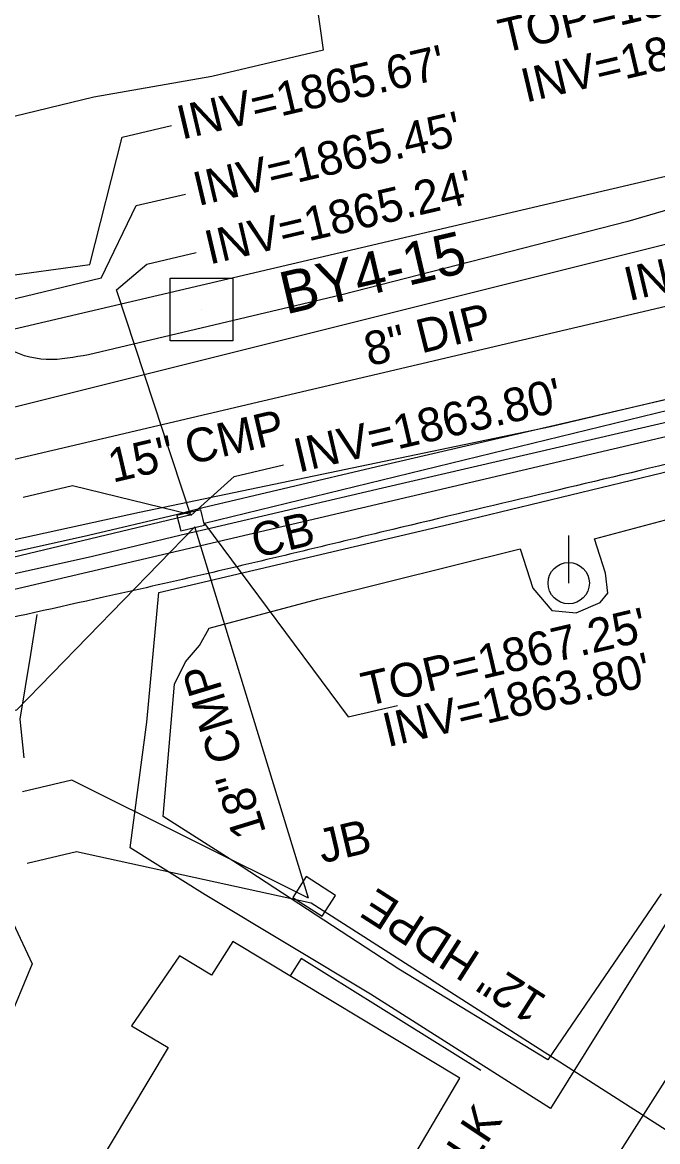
# Model space of a CAD drawing. Extents: x 553786 to 558838, y 502329 to 507342.
# Drawn here: x 557407.1 to 557482.4, y 506598.6 to 506731.1 of the extents above; entities that cross this region are included whole.
import ezdxf

# ---------------------------------------------------------------- set-up
doc = ezdxf.new("R2010")
doc.units = 0
for name, color, linetype in [('CTL Secondary Horizontal and Vertical Text', 7, 'Continuous'), ('Exist Other Culture Fence Line Text', 7, 'Continuous'), ('Exist Structure Minor Catch Basin', 7, 'Continuous'), ('Exist Structure Minor Catch Basin Text', 7, 'Continuous'), ('Exist Structure Minor Catch Basin Top Elevation', 7, 'Continuous'), ('Exist Structure Minor Junction Box', 7, 'Continuous'), ('Exist Structure Minor Junction Box Text', 7, 'Continuous'), ('Exist Structure Minor Pipes CMP 15 Inch', 7, 'Continuous'), ('Exist Structure Minor Pipes CMP 15 Inch Invert', 7, 'Continuous'), ('Exist Structure Minor Pipes CMP 15 Inch Leader', 7, 'Continuous'), ('Exist Structure Minor Pipes CMP 15 Inch Text', 7, 'Continuous'), ('Exist Structure Minor Pipes CMP 18 Inch', 7, 'Continuous'), ('Exist Structure Minor Pipes CMP 18 Inch Invert', 7, 'Continuous'), ('Exist Structure Minor Pipes CMP 18 Inch Leader', 7, 'Continuous'), ('Exist Structure Minor Pipes CMP 18 Inch Text', 7, 'Continuous'), ('Exist Structure Minor Pipes HDPE 12 Inch', 7, 'Continuous'), ('Exist Structure Minor Pipes HDPE 12 Inch Invert', 7, 'Continuous'), ('Exist Structure Minor Pipes HDPE 12 Inch Leader', 7, 'Continuous'), ('Exist Structure Minor Pipes HDPE 12 Inch Text', 7, 'Continuous'), ('Exist Utilities Sanitary Sewer Manhole Text', 7, 'Continuous'), ('Exist Utilities Sanitary Sewer UG Line', 7, 'Continuous'), ('Exist Utilities Sanitary Sewer UG Line Invert Elevation', 7, 'Continuous'), ('Exist Utilities Sanitary Sewer UG Line Text', 7, 'Continuous'), ('Prop CMT Slope Grass', 7, 'Continuous'), ('Prop Drainage Structure Headwall CELL', 7, 'Continuous'), ('Prop Drainage Structure Pipe Alternate 18in', 7, 'Continuous'), ('Prop Drainage Structure Pipe Alternate 24in', 7, 'Continuous'), ('Prop Drainage Structure Pipe Alternate 36in', 7, 'Continuous'), ('Prop Drainage Structure Pipe RCP 15in Class III Label', 7, 'Continuous'), ('Prop Drainage Structure Plot Symbol 50 Scale', 7, 'Continuous'), ('Prop Drainage Structure Tops and Inverts LABEL', 7, 'Continuous'), ('Prop Earthen Structure Tail Ditch Label', 7, 'Continuous'), ('Prop Earthen Structure V Ditch Lateral Detail Label', 7, 'Continuous'), ('Prop Erosion Rip Rap Pad Outlet for Jurisdictional Stream CELL', 7, 'Continuous'), ('Prop Plan Preparation Cover Label', 7, 'Continuous'), ('Sheet Layout Plan Border', 7, 'Continuous')]:
    doc.layers.add(name, color=color, linetype=linetype)

# ---------------------------------------------------------------- blocks, each defined once
blk = doc.blocks.new('CTL SECONDARY HORIZONTAL AND VERTICAL')
at = {"layer": 'Prop Drainage Structure Pipe Alternate 18in'}
blk.add_line((0, 0), (0, 0), dxfattribs=at)
blk.add_lwpolyline([(-0.1043, 0.0004), (0.0005, 0.1052), (0.1055, 0.0002), (0.0007, -0.1047)], close=True, dxfattribs=at)
blk = doc.blocks.new('EXIST UTILITIES POWER POLE')
at = {"layer": 'Prop Plan Preparation Cover Label'}
for q in [(0, 0.1125), (0, 0)]:
    blk.add_line((0, 0), q, dxfattribs=at)
blk.add_circle((0, 0), 0.049, dxfattribs=at)

msp = doc.modelspace()

# ---------------------------------------------------------------- linework, layer by layer
at = {"layer": 'Exist Structure Minor Catch Basin'}
msp.add_lwpolyline([(557425.88, 506670.89), (557428.69, 506671.58), (557428.26, 506673.4), (557425.39, 506672.71), (557425.88, 506670.89)], dxfattribs=at)
at = {"layer": 'Exist Structure Minor Junction Box'}
msp.add_lwpolyline([(557439.14, 506627.51), (557442.6, 506625.28), (557444.19, 506627.73), (557440.72, 506629.97)], close=True, dxfattribs=at)
at = {"layer": 'Exist Structure Minor Pipes CMP 15 Inch'}
for p, q in [((557368.84, 506696.21), (557415.11, 506702.43)), ((557427.07, 506672.71), (557418.25, 506699.46))]:
    msp.add_line(p, q, dxfattribs=at)
at = {"layer": 'Exist Structure Minor Pipes CMP 15 Inch Leader'}
for points in [[(557415.11, 506702.43), (557418.93, 506717.53), (557424.77, 506718.9)], [(557418.25, 506699.46), (557421.83, 506702.48), (557427.67, 506703.85)], [(557427.07, 506672.71), (557432.21, 506677.34), (557438.05, 506678.71)]]:
    msp.add_lwpolyline(points, dxfattribs=at)
at = {"layer": 'Exist Structure Minor Pipes CMP 18 Inch'}
for p, q in [((557526.87, 506695.74), (557428.67, 506671.79)), ((557427.08, 506672.79), (557294.95, 506641.24)), ((557441, 506627.41), (557427.54, 506671.37))]:
    msp.add_line(p, q, dxfattribs=at)
at = {"layer": 'Exist Structure Minor Pipes CMP 18 Inch Leader'}
for points in [[(557427.08, 506672.79), (557413.03, 506676.24), (557407.18, 506674.87)], [(557427.54, 506671.37), (557406.42, 506649.68), (557400.58, 506648.31)], [(557428.67, 506671.79), (557445.69, 506648.87), (557451.53, 506650.24)], [(557441, 506627.41), (557412.95, 506641.38), (557407.1, 506640.01)]]:
    msp.add_lwpolyline(points, dxfattribs=at)
at = {"layer": 'Exist Structure Minor Pipes HDPE 12 Inch'}
for p, q in [((557416.42, 506700.81), (557234.67, 506657.04)), ((557491.48, 506594.74), (557441.33, 506626.82))]:
    msp.add_line(p, q, dxfattribs=at)
at = {"layer": 'Exist Structure Minor Pipes HDPE 12 Inch Leader'}
for points in [[(557416.42, 506700.81), (557420.59, 506709.41), (557426.43, 506710.78)], [(557441.33, 506626.82), (557413.51, 506632.88), (557407.66, 506631.51)]]:
    msp.add_lwpolyline(points, dxfattribs=at)
at = {"layer": 'Exist Utilities Sanitary Sewer UG Line'}
msp.add_line((557366.26, 506675.61), (557525.75, 506715.49), dxfattribs=at)
at = {"layer": 'Prop CMT Slope Grass'}
msp.add_lwpolyline([(557484.11, 506625.69), (557469.65, 506602.51), (557448.36, 506616.05), (557428.77, 506627.8), (557419.88, 506633.36), (557421.86, 506648.27), (557423.28, 506663.61), (557457.71, 506671.7), (557486.46, 506678.63), (557495.52, 506680.8), (557500.18, 506650.87), (557494.7, 506642.63)], dxfattribs=at)
at = {"layer": 'Prop Drainage Structure Headwall CELL'}
msp.add_spline([(557349.66, 506285.99), (557356.68, 506304.83), (557369.49, 506338.98), (557383.09, 506372.99), (557398.1, 506408.04), (557412.26, 506438.22), (557428.64, 506471.13), (557445.79, 506503.68), (557462.92, 506534.76), (557481.94, 506567.34), (557500.9, 506597.37), (557518.14, 506623.31), (557536.7, 506650.1), (557557.52, 506678.2), (557580.81, 506708.65), (557602.41, 506735.48)], degree=3, dxfattribs=at)
at = {"layer": 'Prop Drainage Structure Pipe Alternate 24in'}
msp.add_lwpolyline([(557205.19, 506623.83), (557241.9, 506632.77), (557297.73, 506645.49), (557342.19, 506655.52), (557379.47, 506664.05), (557420.96, 506673.1), (557469.65, 506683.24), (557504.08, 506691.4), (557523.18, 506696.86), (557533.62, 506697.3), (557538.85, 506694.82), (557541.91, 506691.86), (557543.89, 506686.56)], dxfattribs=at)
at = {"layer": 'Prop Drainage Structure Pipe Alternate 36in'}
for points in [[(557511.65, 506717.14), (557478.84, 506707.52), (557444.78, 506698.8), (557414.92, 506691.76)], [(557516.88, 506694.42), (557484.11, 506686.6), (557449.11, 506678.48), (557428.31, 506673.57), (557425.31, 506672.8), (557414.94, 506670.36), (557382.4, 506663.12), (557348.32, 506655.29), (557313.04, 506647.26), (557294.81, 506643.23), (557291.75, 506642.48), (557277.09, 506639.04), (557243.83, 506631.4), (557210.53, 506623.68)]]:
    msp.add_lwpolyline(points, dxfattribs=at)
for points in [[(557414.92, 506691.76), (557409.94, 506691.2), (557405.09, 506692.78), (557402, 506697.34), (557399.62, 506703.23)], [(557458.26, 506483.24), (557463.71, 506493.97), (557480.58, 506524.31), (557499.16, 506556.18), (557518.36, 506586.29), (557535.08, 506610.54), (557553.95, 506637.31), (557574.52, 506663.81), (557596.8, 506691.59)], [(557409.9, 506439.42), (557426.44, 506472.14), (557444.06, 506504.63), (557460.46, 506536.07), (557479.53, 506568.9), (557498.01, 506599.39), (557514.48, 506626.27), (557533.16, 506652.41), (557550.86, 506675.31)]]:
    msp.add_spline(points, degree=3, dxfattribs=at)
at = {"layer": 'Prop Drainage Structure Pipe RCP 15in Class III Label'}
for p, q in [((557204.81, 506647.58), (557576.37, 506734.73)), ((557131.57, 506599.59), (557546.86, 506696.99))]:
    msp.add_line(p, q, dxfattribs=at)
for radius, start in [(1402.39, 139.65), (1462.39, 142.91617)]:
    msp.add_arc((558713.49, 505815.19), radius, start, 158.42006, dxfattribs=at)
at = {"layer": 'Prop Drainage Structure Plot Symbol 50 Scale'}
msp.add_lwpolyline([(557398.51, 506706.65), (557396.97, 506710.95), (557396.56, 506713.18), (557397.66, 506715.5), (557399.16, 506717.61), (557400.74, 506718.7), (557415.55, 506722.28), (557429.54, 506724.73), (557442.76, 506727.85), (557441.25, 506738.81)], dxfattribs=at)
for points in [[(557546.82, 506691.06), (557545.79, 506691.27), (557542.77, 506691.81), (557539.62, 506691.56), (557529.48, 506689.45), (557518.91, 506687.16), (557485.73, 506679.35), (557450.97, 506671.07), (557428.25, 506665.66), (557416.71, 506663.04), (557384.25, 506655.82), (557350.02, 506647.96), (557314.55, 506639.92), (557294.97, 506635.34), (557286.93, 506633.6), (557278.79, 506631.78), (557245.32, 506624.15), (557211.96, 506616.3)], [(557460.49, 506481.98), (557466.14, 506492.68), (557482.75, 506522.9), (557502.05, 506554.58), (557521.67, 506583.9), (557538.82, 506607.98), (557558.64, 506633.42), (557579.68, 506659.52), (557602.79, 506687.14)], [(557464.06, 506480.18), (557469.6, 506490.76), (557486.18, 506520.89), (557505.3, 506552.45), (557524.65, 506581.72), (557542.04, 506605.77), (557561.69, 506631.08), (557582.7, 506657), (557605.66, 506684.42)]]:
    msp.add_spline(points, degree=3, dxfattribs=at)
at = {"layer": 'Prop Drainage Structure Tops and Inverts LABEL'}
msp.add_lwpolyline([(557539.02, 506696.52), (557530, 506694.7), (557526.98, 506694.12), (557517.71, 506691.95), (557484.69, 506684.06), (557449.77, 506675.97), (557428.85, 506671.08), (557425.91, 506670.38), (557415.41, 506667.86), (557382.9, 506660.65), (557348.93, 506652.83), (557313.47, 506644.79), (557295.37, 506640.68), (557292.37, 506639.95), (557290.68, 506639.55)], dxfattribs=at)
at = {"layer": 'Prop Earthen Structure Tail Ditch Label'}
msp.add_lwpolyline([(557461.4, 506607), (557440.13, 506620.25), (557438.83, 506618.22)], dxfattribs=at)
at = {"layer": 'Prop Earthen Structure V Ditch Lateral Detail Label'}
for points in [[(557482.76, 506627.93), (557469.35, 506608.28), (557451.71, 506619.01), (557433.01, 506631.19), (557423.78, 506637.08), (557424.74, 506648.14), (557425.11, 506652.75), (557426.44, 506655.4), (557428.08, 506657.31), (557429.24, 506659.4), (557442.09, 506662.82), (557466.07, 506668.78), (557467.58, 506664.12), (557469.84, 506661.48), (557472.71, 506661.18), (557475.56, 506662.43), (557476.47, 506663.52), (557476.17, 506665.88), (557474.87, 506669.95), (557486.11, 506672.95)], [(557408.81, 506661), (557408.08, 506656.28), (557406.82, 506648.6), (557407.26, 506644.03)], [(557406.03, 506624.46), (557408.28, 506619.62), (557405.24, 506612.28), (557400.03, 506603.46), (557396.69, 506598.27), (557393.37, 506597.18)]]:
    msp.add_lwpolyline(points, dxfattribs=at)
at = {"layer": 'Prop Erosion Rip Rap Pad Outlet for Jurisdictional Stream CELL'}
msp.add_lwpolyline([(557420.15, 506540.33), (557458.94, 506606.11), (557432.04, 506622.29), (557429.5, 506618.31), (557425.7, 506620.57), (557420.03, 506612.31), (557424.37, 506609.73), (557392.64, 506556.72)], close=True, dxfattribs=at)
at = {"layer": 'Sheet Layout Plan Border'}
msp.add_line((557208.23, 506632.98), (557608.72, 506726.91), dxfattribs=at)
msp.add_arc((558713.49, 505815.19), 1432.39, 139.65, 158.42006, dxfattribs=at)

# ---------------------------------------------------------------- block references
at = {"layer": 'Prop Drainage Structure Pipe Alternate 18in', "xscale": 50, "yscale": 49.99999999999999, "rotation": 44.99999999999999}
msp.add_blockref('CTL SECONDARY HORIZONTAL AND VERTICAL', (557428.32, 506697.09), dxfattribs=at)
at = {"layer": 'Prop Plan Preparation Cover Label', "xscale": 50, "yscale": 50}
msp.add_blockref('EXIST UTILITIES POWER POLE', (557471.82, 506664.71), dxfattribs=at)

# ---------------------------------------------------------------- texts
at = {"layer": 'CTL Secondary Horizontal and Vertical Text'}
msp.add_text('BY4-15', height=5, rotation=13.2, dxfattribs=at).set_placement((557438.31, 506696.51))
at = {"layer": 'Exist Other Culture Fence Line Text'}
msp.add_text('60" CH LK', height=4, rotation=56.3342, dxfattribs=at).set_placement((557450.16, 506580.25))
at = {"layer": 'Exist Structure Minor Catch Basin Text'}
msp.add_text('CB', height=4, rotation=13.2, dxfattribs=at).set_placement((557434.77, 506667.67))
at = {"layer": 'Exist Structure Minor Catch Basin Top Elevation'}
msp.add_text("TOP=1867.25'", height=4, rotation=13.2, dxfattribs=at).set_placement((557447.83, 506650.11))
at = {"layer": 'Exist Structure Minor Junction Box Text'}
msp.add_text('JB', height=4, rotation=13.2, dxfattribs=at).set_placement((557442.63, 506631.52))
at = {"layer": 'Exist Structure Minor Pipes CMP 15 Inch Invert'}
for s, p in [("INV=1865.67'", (557425.97, 506717.21)), ("INV=1865.24'", (557429.26, 506702.42)), ("INV=1863.80'", (557439.81, 506677.79))]:
    msp.add_text(s, height=4, rotation=13.2, dxfattribs=at).set_placement(p)
at = {"layer": 'Exist Structure Minor Pipes CMP 15 Inch Text'}
msp.add_text('15" CMP', height=4, rotation=13.2, dxfattribs=at).set_placement((557417.8, 506676.59))
at = {"layer": 'Exist Structure Minor Pipes CMP 18 Inch Invert'}
for s, p in [("INV=1864.38'", (557478.94, 506698.09)), ("INV=1863.80'", (557450.35, 506645.28))]:
    msp.add_text(s, height=4, rotation=13.2, dxfattribs=at).set_placement(p)
at = {"layer": 'Exist Structure Minor Pipes CMP 18 Inch Text'}
msp.add_text('18" CMP', height=4, rotation=107.021, dxfattribs=at).set_placement((557436, 506635.2))
at = {"layer": 'Exist Structure Minor Pipes HDPE 12 Inch Invert'}
msp.add_text("INV=1865.45'", height=4, rotation=13.2, dxfattribs=at).set_placement((557427.9, 506709.35))
at = {"layer": 'Exist Structure Minor Pipes HDPE 12 Inch Text'}
msp.add_text('12" HDPE', height=4, rotation=147.3948, dxfattribs=at).set_placement((557469.42, 506615.69))
at = {"layer": 'Exist Utilities Sanitary Sewer Manhole Text'}
msp.add_text("TOP=1867.71'", height=4, rotation=13.2, dxfattribs=at).set_placement((557464.06, 506727.46))
at = {"layer": 'Exist Utilities Sanitary Sewer UG Line Invert Elevation'}
msp.add_text("INV=1862.71'", height=4, rotation=13.2, dxfattribs=at).set_placement((557466.73, 506721.6))
at = {"layer": 'Exist Utilities Sanitary Sewer UG Line Text'}
msp.add_text('8" DIP', height=4, rotation=14.04, dxfattribs=at).set_placement((557448.19, 506690.35))

doc.saveas('drawing.dxf')
